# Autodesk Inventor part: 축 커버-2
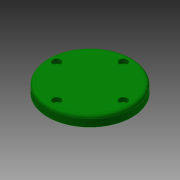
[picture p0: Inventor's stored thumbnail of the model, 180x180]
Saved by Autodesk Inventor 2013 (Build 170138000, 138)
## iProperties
Created: 2015-10
Part Number: 축 커버-2
Document SubType Name: Modeling
Designer: mdu
Density: 7.86 g/cm^3
Material: 강철, 연강
Mass: 456.528 g
Surface Area: 143.652 cm^2
Volume: 58.0824 cm^3
Author: mdu
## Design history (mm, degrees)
sketch "스케치1"
  geometry: C1 r 41 at (0, 0); C2 r 26 at (0, 0) reference; 1 further point
  constraints: 1 centre point, 1 coincident
  dimensions: "d31" = 82 diameter of C1
  node "참조2"
extrude "돌출1" new body sketch "스케치1" distance "d0" = 10; taper "d1" = 0 deg
extrude "돌출2" join sketch "스케치1" distance "d2" = 5; taper "d3" = 0 deg
sketch "스케치2"
  geometry: C1 r 20 at (0, 0); 1 further point
  constraints: 1 centre point, 1 coincident
  dimensions: "d13" = 40 diameter of C1
extrude "돌출3" cut sketch "스케치2" distance "d14" = 3; taper "d15" = 0 deg
sketch "스케치3"
  geometry: C1 r 1.621 at (0, 32.5) reference; 1 further point
hole "구멍2" sketch "스케치3" at (0, 32.5) diameter "d16" = 4.5; stored, may be unused: countersink angle "d20" = 90 deg, drill point angle "d22" = 118 deg; dims "d17" = 6, "d18" = 8, "d19" = 4.4, "d21" = 8
fillet "모깎기1" dims "d26" = 3, "d27" = 0.3
chamfer "모따기1" distance "d28" = 1; stored, may be unused: second distance "d29" = 2, angle "d30" = 45 deg
node "솔리드1"
pattern_circular "원형 패턴1" dims angle "d24" = 360 deg
node "참조3"
